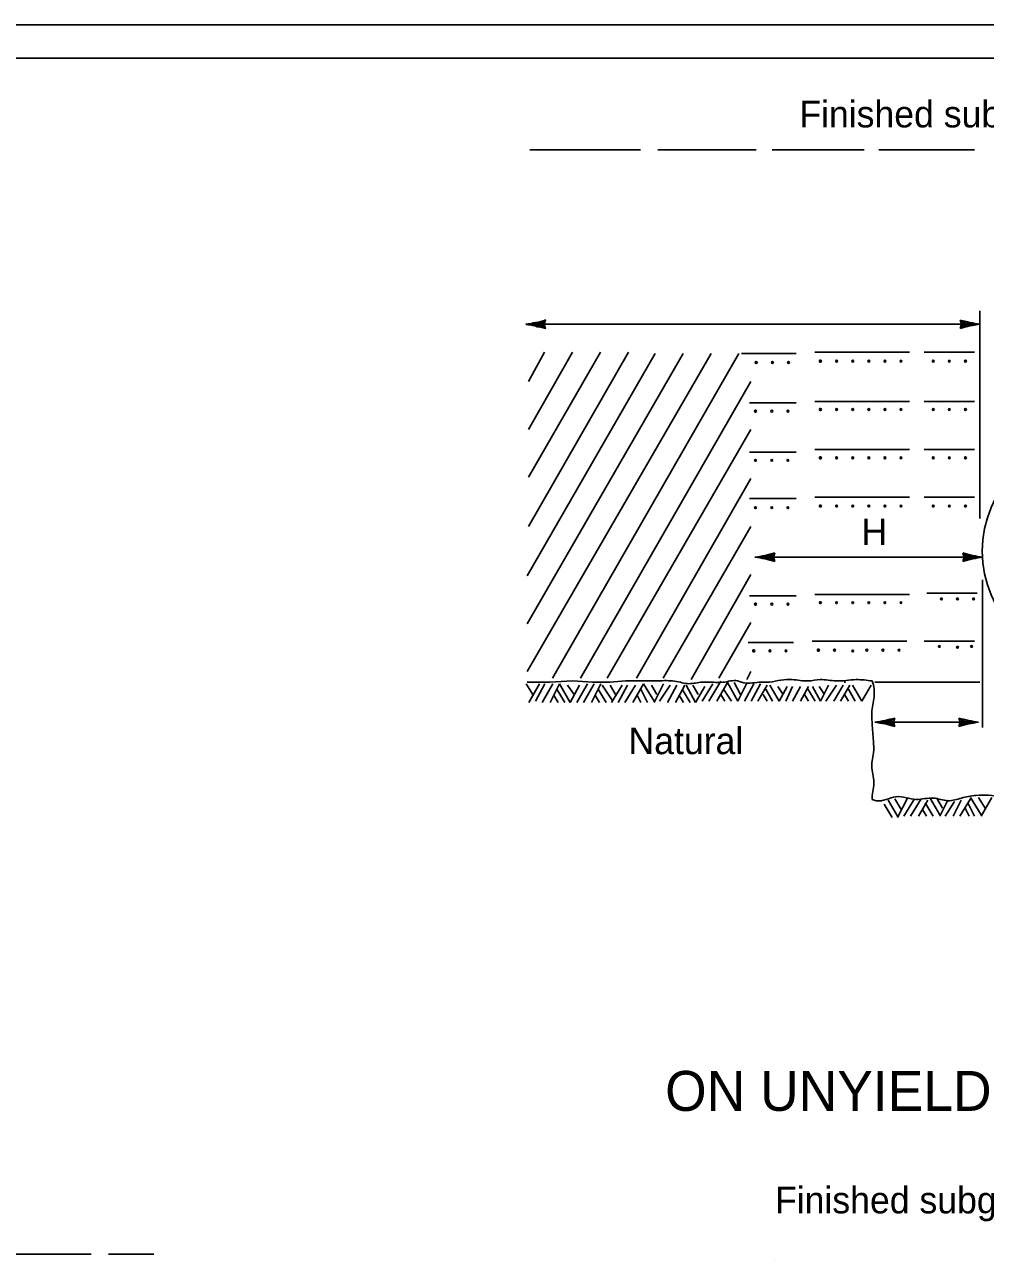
# Model space of a CAD drawing. Extents: x 0 to 390, y 0 to 265.
# Drawn here: x 134.4 to 206.6, y 172.1 to 265 of the extents above; entities that cross this region are included whole.
import ezdxf

# ---------------------------------------------------------------- set-up
doc = ezdxf.new("R2010")
doc.units = 0
doc.layers.add('D_Details', color=7, linetype='Continuous')
doc.layers.add('Default', color=7, linetype='Continuous')

msp = doc.modelspace()

# ---------------------------------------------------------------- linework, layer by layer
at = {"layer": 'D_Details'}
for p, q in [((180.654, 255.601), (172.354, 255.601)), ((189.354, 255.601), (181.954, 255.601)), ((197.454, 255.601), (190.554, 255.601)), ((198.554, 255.601), (205.754, 255.601)), ((206.154, 227.901), (206.154, 243.501)), ((172.054, 242.501), (206.154, 242.501)), ((172.154, 216.401), (185.954, 240.301)), ((172.154, 220.001), (183.854, 240.301)), ((172.154, 223.601), (181.754, 240.301)), ((172.254, 227.301), (179.754, 240.401)), ((172.254, 231.001), (177.654, 240.401)), ((172.254, 234.601), (175.554, 240.401)), ((172.254, 238.201), (173.454, 240.401)), ((174.054, 215.901), (188.054, 240.301)), ((188.254, 240.301), (192.354, 240.301)), ((193.754, 240.401), (200.854, 240.401)), ((201.954, 240.401), (205.754, 240.401)), ((176.154, 215.901), (188.954, 238.201)), ((188.854, 236.601), (192.354, 236.601)), ((193.754, 236.701), (200.854, 236.701)), ((201.954, 236.701), (205.754, 236.701)), ((178.154, 215.901), (188.954, 234.601)), ((188.854, 232.901), (192.354, 232.901)), ((193.754, 233.101), (200.854, 233.101)), ((201.954, 233.101), (205.754, 233.101)), ((180.354, 215.901), (188.954, 230.901)), ((193.754, 229.501), (200.854, 229.501)), ((201.954, 229.501), (205.754, 229.501)), ((188.854, 229.401), (192.354, 229.401)), ((182.354, 215.901), (188.954, 227.301)), ((189.254, 225.001), (206.354, 225.001)), ((184.454, 215.801), (188.954, 223.701)), ((206.354, 223.301), (206.354, 212.201)), ((188.854, 222.101), (192.354, 222.101)), ((193.754, 222.201), (200.854, 222.201)), ((202.154, 222.301), (205.954, 222.301)), ((186.554, 215.901), (188.954, 220.101)), ((188.754, 218.601), (192.154, 218.601)), ((193.554, 218.701), (200.654, 218.701)), ((201.954, 218.701), (205.754, 218.701)), ((184.154, 215.601), (184.154, 215.601)), ((185.781, 214.19), (186.681, 215.69)), ((186.381, 214.19), (187.181, 215.59)), ((187.981, 214.19), (187.181, 215.59)), ((188.181, 214.69), (187.681, 215.59)), ((187.981, 214.19), (188.681, 215.59)), ((188.654, 215.801), (188.954, 216.401)), ((190.854, 215.701), (190.854, 215.701)), ((196.054, 215.601), (195.954, 215.601)), ((198.254, 215.601), (206.154, 215.601)), ((172.581, 214.69), (172.081, 215.49)), ((172.281, 214.09), (173.081, 215.49)), ((172.554, 215.501), (172.554, 215.501)), ((172.781, 214.19), (173.481, 215.49)), ((173.281, 214.09), (174.081, 215.49)), ((173.881, 214.09), (174.581, 215.49)), ((174.481, 214.09), (174.181, 214.59)), ((174.981, 214.09), (174.381, 215.09)), ((175.381, 214.09), (174.581, 215.49)), ((175.681, 214.69), (175.181, 215.39)), ((175.381, 214.09), (176.081, 215.39)), ((175.881, 214.09), (176.681, 215.49)), ((176.381, 214.09), (177.181, 215.49)), ((176.981, 214.09), (177.681, 215.49)), ((177.581, 214.09), (177.281, 214.59)), ((178.081, 214.09), (177.481, 215.09)), ((178.581, 214.19), (177.781, 215.39)), ((178.781, 214.69), (178.381, 215.39)), ((178.481, 214.09), (179.281, 215.39)), ((178.981, 214.09), (179.681, 215.39)), ((179.481, 214.09), (180.281, 215.39)), ((180.081, 214.09), (180.881, 215.49)), ((180.681, 214.09), (180.381, 214.69)), ((181.181, 214.09), (180.681, 215.09)), ((181.681, 214.19), (180.881, 215.49)), ((181.881, 214.69), (181.481, 215.39)), ((181.681, 214.09), (182.381, 215.49)), ((182.081, 214.19), (182.881, 215.39)), ((182.681, 214.09), (183.381, 215.39)), ((183.281, 214.09), (183.981, 215.39)), ((183.881, 214.09), (183.581, 214.59)), ((184.381, 214.09), (183.781, 215.09)), ((184.781, 214.09), (184.081, 215.39)), ((184.981, 214.69), (184.581, 215.39)), ((184.781, 214.09), (185.481, 215.29)), ((185.281, 214.19), (186.081, 215.49)), ((186.981, 214.19), (186.681, 214.69)), ((187.481, 214.19), (186.881, 215.09)), ((188.481, 214.19), (189.181, 215.49)), ((188.981, 214.19), (189.681, 215.49)), ((189.481, 214.19), (190.181, 215.39)), ((190.181, 214.19), (189.881, 214.69)), ((190.581, 214.19), (190.081, 215.09)), ((191.081, 214.19), (190.381, 215.39)), ((191.381, 214.69), (190.981, 215.29)), ((191.081, 214.19), (191.681, 215.29)), ((191.581, 214.19), (192.081, 215.29)), ((192.081, 214.19), (192.681, 215.29)), ((192.681, 214.19), (193.281, 215.29)), ((193.281, 214.19), (192.981, 214.69)), ((193.781, 214.19), (193.181, 215.19)), ((194.181, 214.19), (193.581, 215.29)), ((194.481, 214.69), (194.081, 215.29)), ((194.181, 214.19), (194.781, 215.39)), ((194.581, 214.19), (195.381, 215.39)), ((195.181, 214.19), (195.881, 215.39)), ((195.681, 214.19), (196.381, 215.39)), ((196.281, 214.19), (195.981, 214.69)), ((196.781, 214.19), (196.281, 215.09)), ((197.281, 214.19), (196.581, 215.39)), ((197.281, 214.19), (197.981, 215.39)), ((198.054, 215.301), (198.054, 215.301)), ((198.254, 214.701), (198.254, 214.701)), ((198.254, 214.501), (198.254, 214.501)), ((198.254, 212.601), (206.054, 212.601)), ((199.354, 212.701), (199.354, 212.701)), ((198.054, 210.801), (198.054, 210.801)), ((199.547, 205.454), (198.947, 206.454)), ((199.947, 205.554), (199.247, 206.754)), ((200.247, 206.054), (199.747, 206.854)), ((199.947, 205.454), (200.747, 206.954)), ((200.054, 206.901), (200.054, 206.901)), ((200.447, 205.554), (201.247, 206.854)), ((200.947, 205.554), (201.747, 206.854)), ((201.547, 205.554), (202.247, 206.754)), ((202.647, 205.554), (202.047, 206.554)), ((203.147, 205.654), (202.447, 206.854)), ((203.347, 206.154), (202.947, 206.854)), ((203.147, 205.554), (203.747, 206.754)), ((203.547, 205.554), (204.247, 206.654)), ((204.147, 205.554), (204.747, 206.754)), ((204.647, 205.554), (205.447, 206.854)), ((205.747, 205.554), (205.247, 206.554)), ((206.247, 205.654), (205.447, 206.954)), ((206.547, 206.154), (206.047, 206.954)), ((206.247, 205.554), (207.047, 206.954)), ((202.147, 205.554), (201.847, 206.054)), ((205.347, 205.554), (205.047, 206.154)), ((131.817, 172.634), (139.417, 172.634)), ((140.717, 172.634), (144.117, 172.634)), ((190.754, 172.201), (190.754, 172.201))]:
    msp.add_line(p, q, dxfattribs=at)
for points in [[(173.454, 242.501), (173.454, 242.501), (172.054, 242.501), (172.054, 242.501)], [(173.454, 242.601), (172.554, 242.601)], [(173.454, 242.601), (172.854, 242.601)], [(173.454, 242.701), (173.154, 242.701)], [(173.554, 242.801), (173.454, 242.801)], [(173.454, 242.401), (172.554, 242.401)], [(173.454, 242.301), (172.854, 242.301)], [(173.454, 242.301), (173.154, 242.301)], [(173.554, 242.201), (173.454, 242.201)], [(181.854, 215.701), (179.554, 215.701), (178.354, 215.601), (177.054, 215.601), (175.554, 215.701), (173.854, 215.601), (172.454, 215.601), (172.154, 215.601)]]:
    msp.add_lwpolyline(points, dxfattribs=at)
for centre, radius in [((189.34, 239.623), 0.0674), ((189.357, 239.623), 0.0674), ((190.567, 239.623), 0.0674), ((191.776, 239.623), 0.0674), ((194.16, 239.723), 0.0674), ((194.177, 239.723), 0.0674), ((195.386, 239.723), 0.0674), ((196.596, 239.723), 0.0674), ((197.805, 239.723), 0.0674), ((199.015, 239.723), 0.0674), ((200.224, 239.723), 0.0674), ((202.643, 239.723), 0.0674), ((203.853, 239.723), 0.0674), ((205.063, 239.723), 0.0674), ((189.293, 235.973), 0.0674), ((189.31, 235.973), 0.0674), ((190.519, 235.973), 0.0674), ((191.729, 235.973), 0.0674), ((194.16, 236.094), 0.0674), ((194.177, 236.094), 0.0674), ((195.386, 236.094), 0.0674), ((196.596, 236.094), 0.0674), ((197.805, 236.094), 0.0674), ((199.015, 236.094), 0.0674), ((200.224, 236.094), 0.0674), ((202.643, 236.094), 0.0674), ((203.853, 236.094), 0.0674), ((205.063, 236.094), 0.0674), ((214.775, 225.446), 8.447), ((189.293, 232.275), 0.0674), ((189.31, 232.275), 0.0674), ((190.519, 232.275), 0.0674), ((191.729, 232.275), 0.0674), ((194.16, 232.466), 0.0674), ((194.177, 232.466), 0.0674), ((195.386, 232.466), 0.0674), ((196.596, 232.466), 0.0674), ((197.805, 232.466), 0.0674), ((199.015, 232.466), 0.0674), ((200.224, 232.466), 0.0674), ((202.643, 232.466), 0.0674), ((203.853, 232.466), 0.0674), ((205.063, 232.466), 0.0674), ((189.293, 228.72), 0.0674), ((189.31, 228.72), 0.0674), ((190.519, 228.72), 0.0674), ((191.729, 228.72), 0.0674), ((194.16, 228.837), 0.0674), ((194.177, 228.837), 0.0674), ((195.386, 228.837), 0.0674), ((196.596, 228.837), 0.0674), ((197.805, 228.837), 0.0674), ((199.015, 228.837), 0.0674), ((200.224, 228.837), 0.0674), ((202.643, 228.837), 0.0674), ((203.853, 228.837), 0.0674), ((205.063, 228.837), 0.0674), ((189.293, 221.467), 0.0674), ((189.31, 221.467), 0.0674), ((190.519, 221.467), 0.0674), ((191.729, 221.467), 0.0674), ((194.16, 221.58), 0.0674), ((194.177, 221.58), 0.0674), ((195.386, 221.58), 0.0674), ((196.596, 221.58), 0.0674), ((197.805, 221.58), 0.0674), ((199.015, 221.58), 0.0674), ((200.224, 221.58), 0.0674), ((203.255, 221.862), 0.0674), ((204.465, 221.862), 0.0674), ((205.675, 221.862), 0.0674), ((203.102, 218.295), 0.0674), ((205.522, 218.295), 0.0674), ((189.151, 217.959), 0.0674), ((189.167, 217.959), 0.0674), ((190.377, 217.959), 0.0674), ((191.586, 217.959), 0.0674), ((194.007, 218.012), 0.0674), ((194.024, 218.012), 0.0674), ((195.233, 218.012), 0.0674), ((196.596, 217.951), 0.0674), ((197.652, 218.012), 0.0674), ((198.862, 218.012), 0.0674), ((200.071, 218.012), 0.0674), ((204.465, 218.234), 0.0674)]:
    msp.add_circle(centre, radius, dxfattribs=at)
for centre, radius, start, end in [((170.56, 253.27), 10.886, 278, 285.81169), ((170.56, 231.71), 10.886, 74.18653, 82), ((174.13, 242.49), 0.676, 153.215, 206.78499), ((207.719, 253.641), 11.25, 254.18653, 262), ((204.03, 242.501), 0.699, 333.215, 26.78499), ((207.719, 231.36), 11.25, 98, 105.81169), ((207.719, 253.641), 11.35, 254.56992, 258.99901), ((207.719, 231.36), 11.35, 101.00099, 105.43008), ((207.719, 253.641), 11.45, 254.82908, 256.64064), ((207.719, 231.36), 11.45, 103.35937, 105.17092), ((187.688, 236.141), 11.25, 278, 285.81169), ((187.688, 213.86), 11.25, 74.18653, 82), ((187.688, 236.141), 11.35, 281.00099, 285.43008), ((187.688, 213.86), 11.35, 74.56992, 78.99901), ((187.688, 236.141), 11.45, 283.35937, 285.17092), ((187.688, 213.86), 11.45, 74.82908, 76.64064), ((191.378, 225.001), 0.699, 153.215, 206.78499), ((207.919, 236.141), 11.25, 254.18653, 262), ((204.23, 225.001), 0.699, 333.215, 26.78499), ((207.919, 213.86), 11.25, 98, 105.81169), ((207.919, 236.141), 11.35, 254.56992, 258.99901), ((207.919, 213.86), 11.35, 101.00099, 105.43008), ((207.919, 236.141), 11.45, 254.82908, 256.64064), ((207.919, 213.86), 11.45, 103.35937, 105.17092), ((196.688, 223.741), 11.25, 278, 285.81169), ((196.688, 223.741), 11.35, 281.00099, 285.43008), ((200.378, 212.601), 0.699, 153.215, 206.78499), ((207.619, 223.741), 11.25, 254.18653, 262), ((203.93, 212.601), 0.699, 333.215, 26.78499), ((207.619, 223.741), 11.35, 254.56992, 258.99901), ((196.688, 201.46), 11.25, 74.18653, 82), ((196.688, 201.46), 11.35, 74.56992, 78.99901), ((196.688, 223.741), 11.45, 283.35937, 285.17092), ((196.688, 201.46), 11.45, 74.82908, 76.64064), ((207.619, 201.46), 11.25, 98, 105.81169), ((207.619, 201.46), 11.35, 101.00099, 105.43008), ((207.619, 223.741), 11.45, 254.82908, 256.64064), ((207.619, 201.46), 11.45, 103.35937, 105.17092)]:
    msp.add_arc(centre, radius, start, end, dxfattribs=at)
for points in [[(190.354, 215.601), (189.554, 215.601), (188.254, 215.601), (187.954, 215.701), (186.854, 215.601), (186.154, 215.601), (185.154, 215.601), (184.154, 215.501), (183.654, 215.601), (183.054, 215.701), (181.854, 215.701)], [(190.354, 215.601), (192.054, 215.801), (193.254, 215.701), (194.154, 215.801), (195.354, 215.701), (196.854, 215.801), (198.054, 215.701)], [(198.054, 215.701), (198.154, 215.401), (198.154, 214.201), (198.054, 213.601), (198.054, 212.501), (198.154, 211.201), (198.154, 210.301), (198.054, 209.701), (198.054, 209.001), (198.154, 208.401), (198.154, 207.701), (198.054, 207.101), (198.054, 206.801)], [(198.054, 206.801), (198.354, 206.701), (199.854, 207.001), (201.354, 206.801), (202.654, 206.901), (203.754, 206.701), (204.754, 206.901), (205.854, 207.101), (207.754, 207.001), (209.254, 206.801), (210.254, 207.001), (211.954, 206.901), (213.354, 206.901), (214.254, 207.001), (214.854, 206.901), (216.254, 206.901), (218.854, 206.801), (219.154, 206.901)]]:
    msp.add_spline(points, degree=3, dxfattribs=at)
at = {"layer": 'Default'}
for points in [[(0, 265), (326.25, 265), (326.25, 255), (390, 255), (390, 37.5), (315, 37.5), (315, 0), (0, 0)], [(0, 262.5), (326.25, 262.5), (326.25, 252.5), (390, 252.5), (390, 40), (315, 40), (315, 2.5), (0, 2.5)]]:
    msp.add_lwpolyline(points, close=True, dxfattribs=at)

# ---------------------------------------------------------------- texts
at = {"layer": 'D_Details'}
for s, height, p in [('Finished subgrade', 2, (192.582, 257.286)), ('H', 2, (197.257, 225.902)), ('Natural', 2, (179.757, 210.202)), ('ON UNYIELDING MATERIAL', 3, (182.508, 183.402)), ('Finished subgrade', 2, (190.757, 175.702))]:
    msp.add_text(s, height=height, dxfattribs=at).set_placement(p)

doc.saveas('drawing.dxf')
